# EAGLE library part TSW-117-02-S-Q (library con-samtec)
THROUGH-HOLE .025" SQ POST HEADER Source: Samtec TSW.pdf
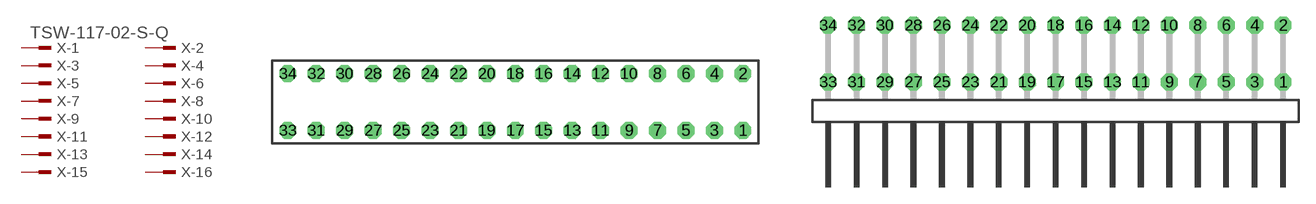
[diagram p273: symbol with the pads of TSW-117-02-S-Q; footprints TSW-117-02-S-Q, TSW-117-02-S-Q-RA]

Designator prefix X; gates -1=MPINV -2=MPIN -3=MPIN -4=MPIN -5=MPIN -6=MPIN -7=MPIN -8=MPIN -9=MPIN -10=MPIN -11=MPIN -12=MPIN -13=MPIN -14=MPIN -15=MPIN -16=MPIN -17=MPIN -18=MPIN -19=MPIN -20=MPIN -21=MPIN -22=MPIN -23=MPIN -24=MPIN -25=MPIN -26=MPIN -27=MPIN -28=MPIN -29=MPIN -30=MPIN -31=MPIN -32=MPIN -33=MPIN -34=MPIN

## TSW-117-02-S-Q (OC_FARNELL: unknown; OC_NEWARK: unknown)  [TSW-117-02-S-Q]
1  -1:1  pas
2  -2:1  pas
3  -3:1  pas
4  -4:1  pas
5  -5:1  pas
6  -6:1  pas
7  -7:1  pas
8  -8:1  pas
9  -9:1  pas
10  -10:1  pas
11  -11:1  pas
12  -12:1  pas
13  -13:1  pas
14  -14:1  pas
15  -15:1  pas
16  -16:1  pas
17  -17:1  pas
18  -18:1  pas
19  -19:1  pas
20  -20:1  pas
21  -21:1  pas
22  -22:1  pas
23  -23:1  pas
24  -24:1  pas
25  -25:1  pas
26  -26:1  pas
27  -27:1  pas
28  -28:1  pas
29  -29:1  pas
30  -30:1  pas
31  -31:1  pas
32  -32:1  pas
33  -33:1  pas
34  -34:1  pas

## TSW-117-02-S-Q-RA (OC_FARNELL: unknown; OC_NEWARK: unknown)  [TSW-117-02-S-Q-RA]
Pads as for TSW-117-02-S-Q

## Footprint TSW-117-02-S-Q (pad centres in mm)
THROUGH-HOLE .025" SQ POST HEADER Source: Samtec TSW.pdf
drill 1 pad 1.5 octagon: 1 20.32,-2.54; 2 20.32,2.54; 3 17.78,-2.54; 4 17.78,2.54; 5 15.24,-2.54; 6 15.24,2.54; 7 12.7,-2.54; 8 12.7,2.54; 9 10.16,-2.54; 10 10.16,2.54; 11 7.62,-2.54; 12 7.62,2.54; 13 5.08,-2.54; 14 5.08,2.54; 15 2.54,-2.54; 16 2.54,2.54; 17 0,-2.54; 18 0,2.54; 19 -2.54,-2.54; 20 -2.54,2.54; 21 -5.08,-2.54; 22 -5.08,2.54; 23 -7.62,-2.54; 24 -7.62,2.54; 25 -10.16,-2.54; 26 -10.16,2.54; 27 -12.7,-2.54; 28 -12.7,2.54; 29 -15.24,-2.54; 30 -15.24,2.54; 31 -17.78,-2.54; 32 -17.78,2.54; 33 -20.32,-2.54; 34 -20.32,2.54

## Footprint TSW-117-02-S-Q-RA (pad centres in mm)
THROUGH-HOLE .025" SQ POST HEADER Source: Samtec TSW.pdf
drill 1 pad 1.5 octagon: 1 20.32,1.524; 2 20.32,6.604; 3 17.78,1.524; 4 17.78,6.604; 5 15.24,1.524; 6 15.24,6.604; 7 12.7,1.524; 8 12.7,6.604; 9 10.16,1.524; 10 10.16,6.604; 11 7.62,1.524; 12 7.62,6.604; 13 5.08,1.524; 14 5.08,6.604; 15 2.54,1.524; 16 2.54,6.604; 17 0,1.524; 18 0,6.604; 19 -2.54,1.524; 20 -2.54,6.604; 21 -5.08,1.524; 22 -5.08,6.604; 23 -7.62,1.524; 24 -7.62,6.604; 25 -10.16,1.524; 26 -10.16,6.604; 27 -12.7,1.524; 28 -12.7,6.604; 29 -15.24,1.524; 30 -15.24,6.604; 31 -17.78,1.524; 32 -17.78,6.604; 33 -20.32,1.524; 34 -20.32,6.604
